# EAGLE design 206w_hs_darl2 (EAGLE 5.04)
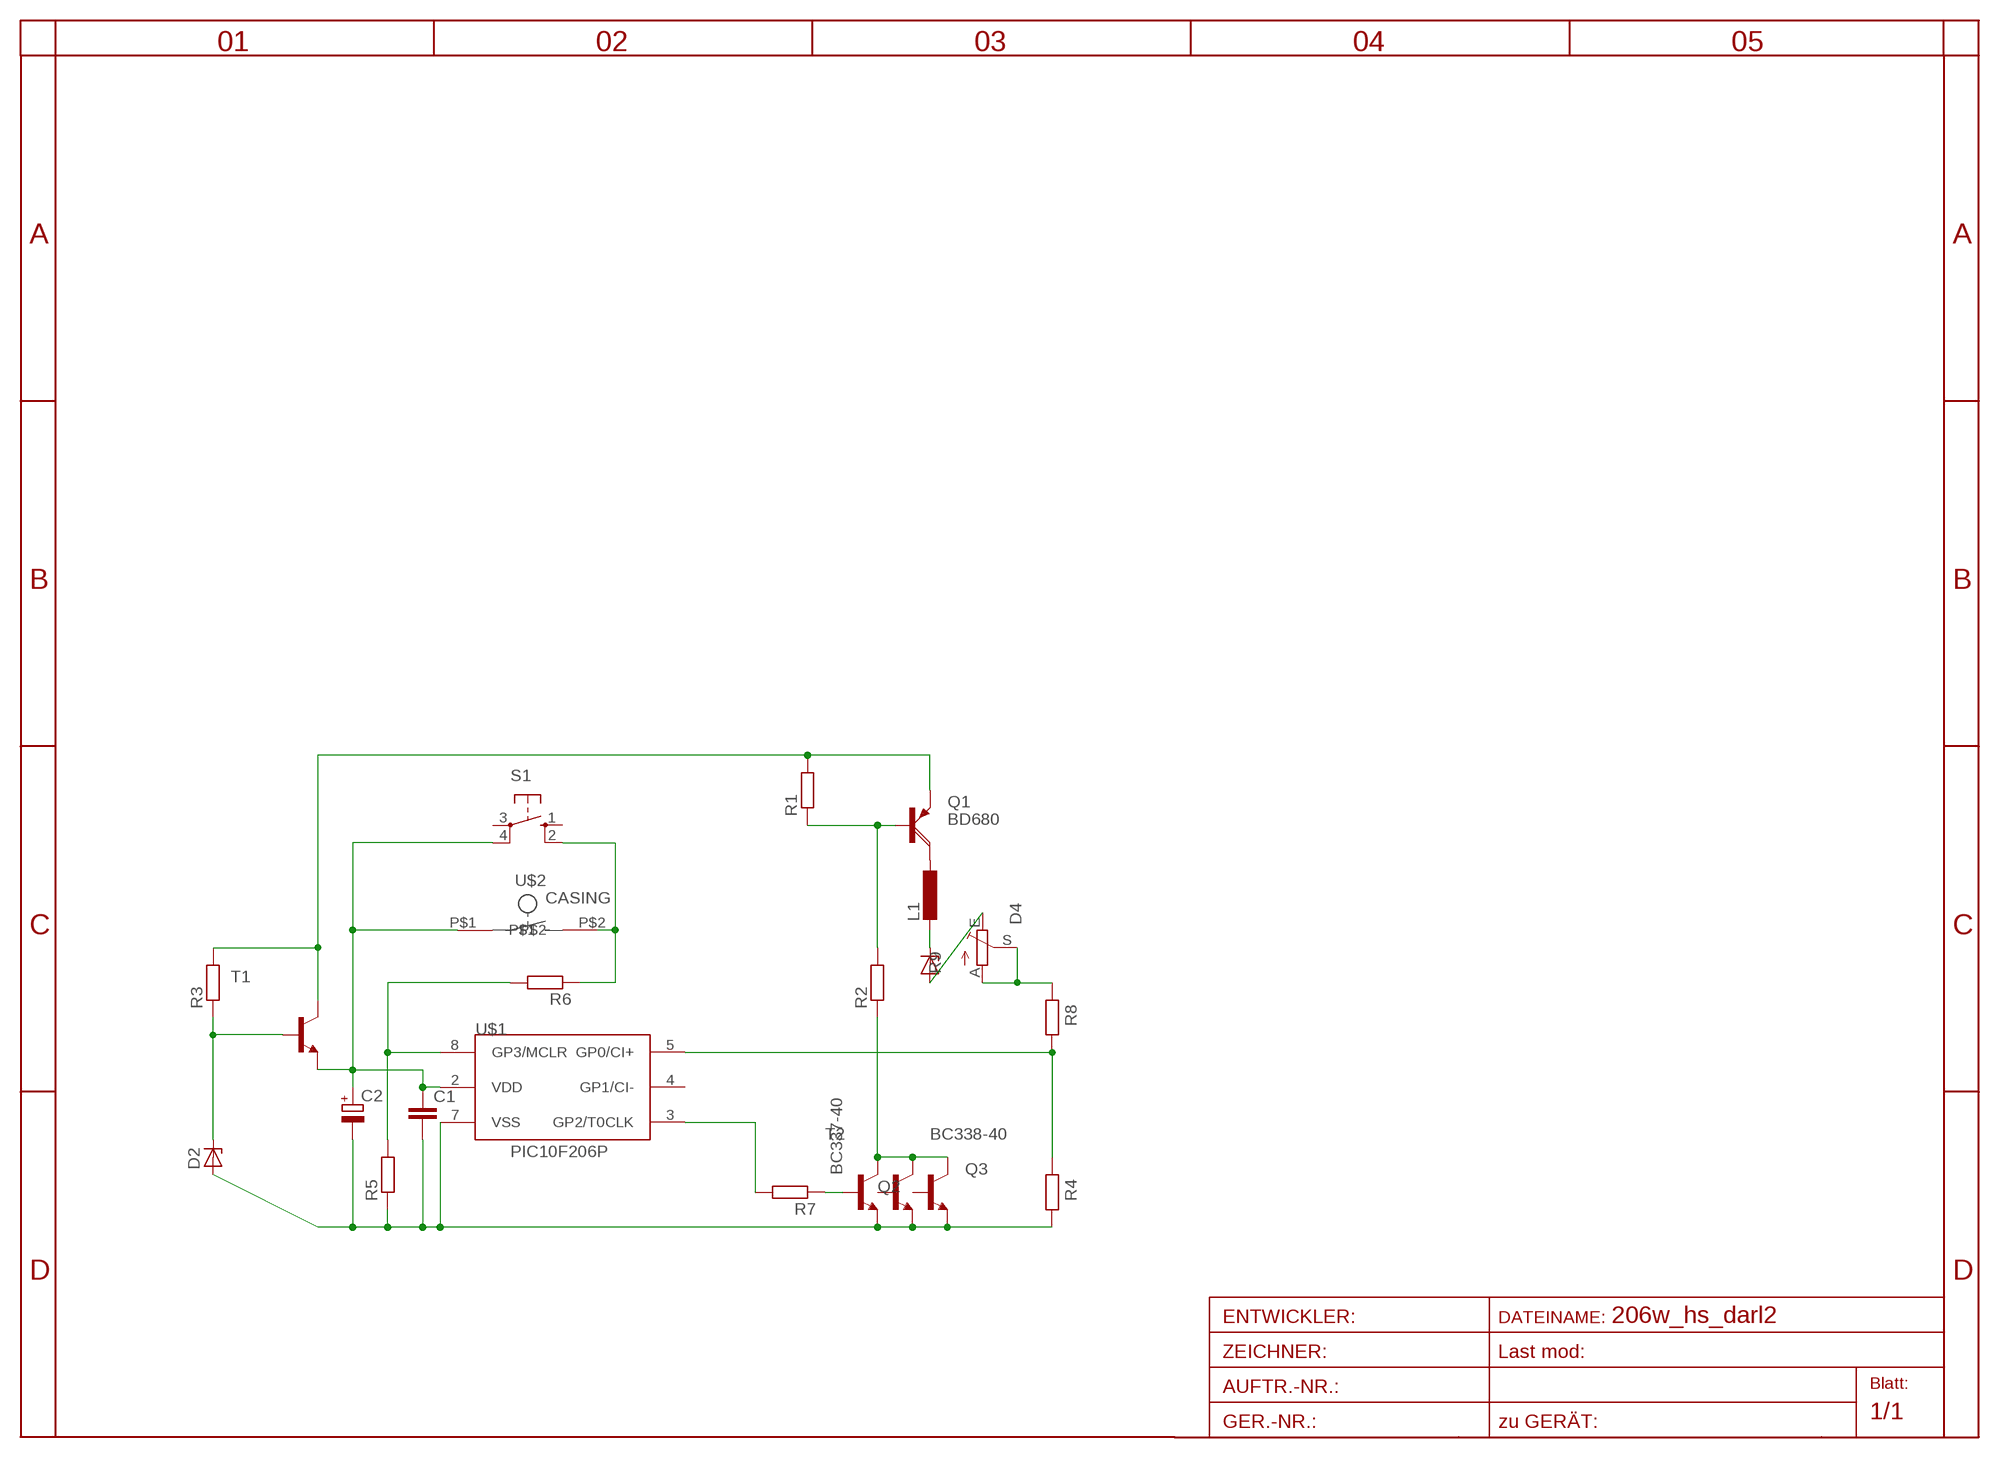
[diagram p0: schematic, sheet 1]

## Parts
C1  C-EU025-025X050  [C025-025X050]
C2  CPOL-EUE2.5-5  [E2,5-5]
D2  ZENER-DIODEZD-7.5  [ZDIO-7.5]
D4  ZENER-DIODEZD-12.5  [ZDIO12.5]
L1  L-EU2200-12.7  [2200-12.7]
Q1  BD680  [TO126AV]
Q2  BC337-40  [TO92]
Q3  BC338-40  [TO92-EBC]
R1  R-EU_0204/7  [0204/7]
R2  R-EU_0204/7  [0204/7]
R3  R-EU_0204/7  [0204/7]
R4  R-EU_0204/7  [0204/7]
R5  R-EU_0204/7  [0204/7]
R6  R-EU_0204/7  [0204/7]
R7  R-EU_0204/7  [0204/7]
R8  R-EU_0204/7  [0204/7]
R9  TRIM_EU-CA6V  [CA6V]
S1  10-XX  [B3F-10XX]
T1  -NPN-TO92-BCE  [TO92-BCE]
T2  -NPN-TO92-BCE  [TO92-BCE]
U$1  PIC10F206P  [DIL8]
U$2  CASING  [CASING]

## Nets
GND: C1.2 C2.- D2.A Q2.1(E) Q3.E R4.1 R5.1 T2.E U$1.7(VSS)
N$1: R8.2 R9.A R9.S
N$2: C1.1 C2.+ S1.4(P1) T1.E U$1.2(VDD) U$2.P$1
N$3: L1.1 Q1.C
N$5: R5.2 R6.2 U$1.8(GP3/MCLR)
N$7: R6.1 S1.2(S1) U$2.P$2
N$8: D2.C R3.1 T1.B
N$9: R7.2 U$1.3(GP2/T0CLK)
N$10: Q2.2(B) R7.1
N$11: Q2.3(C) Q3.C R2.1 T2.C
N$12: D4.A R9.E
N$13: Q1.B R1.1 R2.2
N$14: R4.2 R8.1 U$1.5(GP0/CI+)
N$15: D4.C L1.2
V60: Q1.E R1.2 R3.2 T1.C
Unconnected: Q3.B S1.1(S) S1.3(P) T2.B U$1.4(GP1/CI-)

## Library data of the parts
C1 = rcl:C-EU: CAPACITOR, European symbol
C2 = rcl:CPOL-EU: POLARIZED CAPACITOR, European symbol
D2 D4 = diode-1:ZENER-DIODE: Z-Diode
L1 = rcl-2:L-EU: INDUCTOR, European symbol
Q1 = transistor-power:BD680: PNP DARLINGTON TRANSISTOR
Q2 = transistor-npn:BC337*: NPN Transistor
Q3 = transistor-npn:BC338*: NPN Transistor
R1-R8 = rcl:R-EU_: RESISTOR, European symbol
R9 = pot:TRIM_EU-: POTENTIOMETER
S1 = switch-omron:10-XX: OMRON SWITCH
T1 T2 = transistor-neu-to92:*-NPN-: NPN Transistror
U$1 = microchip-5:PIC10F2*: uPC nW 0,25/0,5k Program Flash memory Comparator
U$2 = button:CASING

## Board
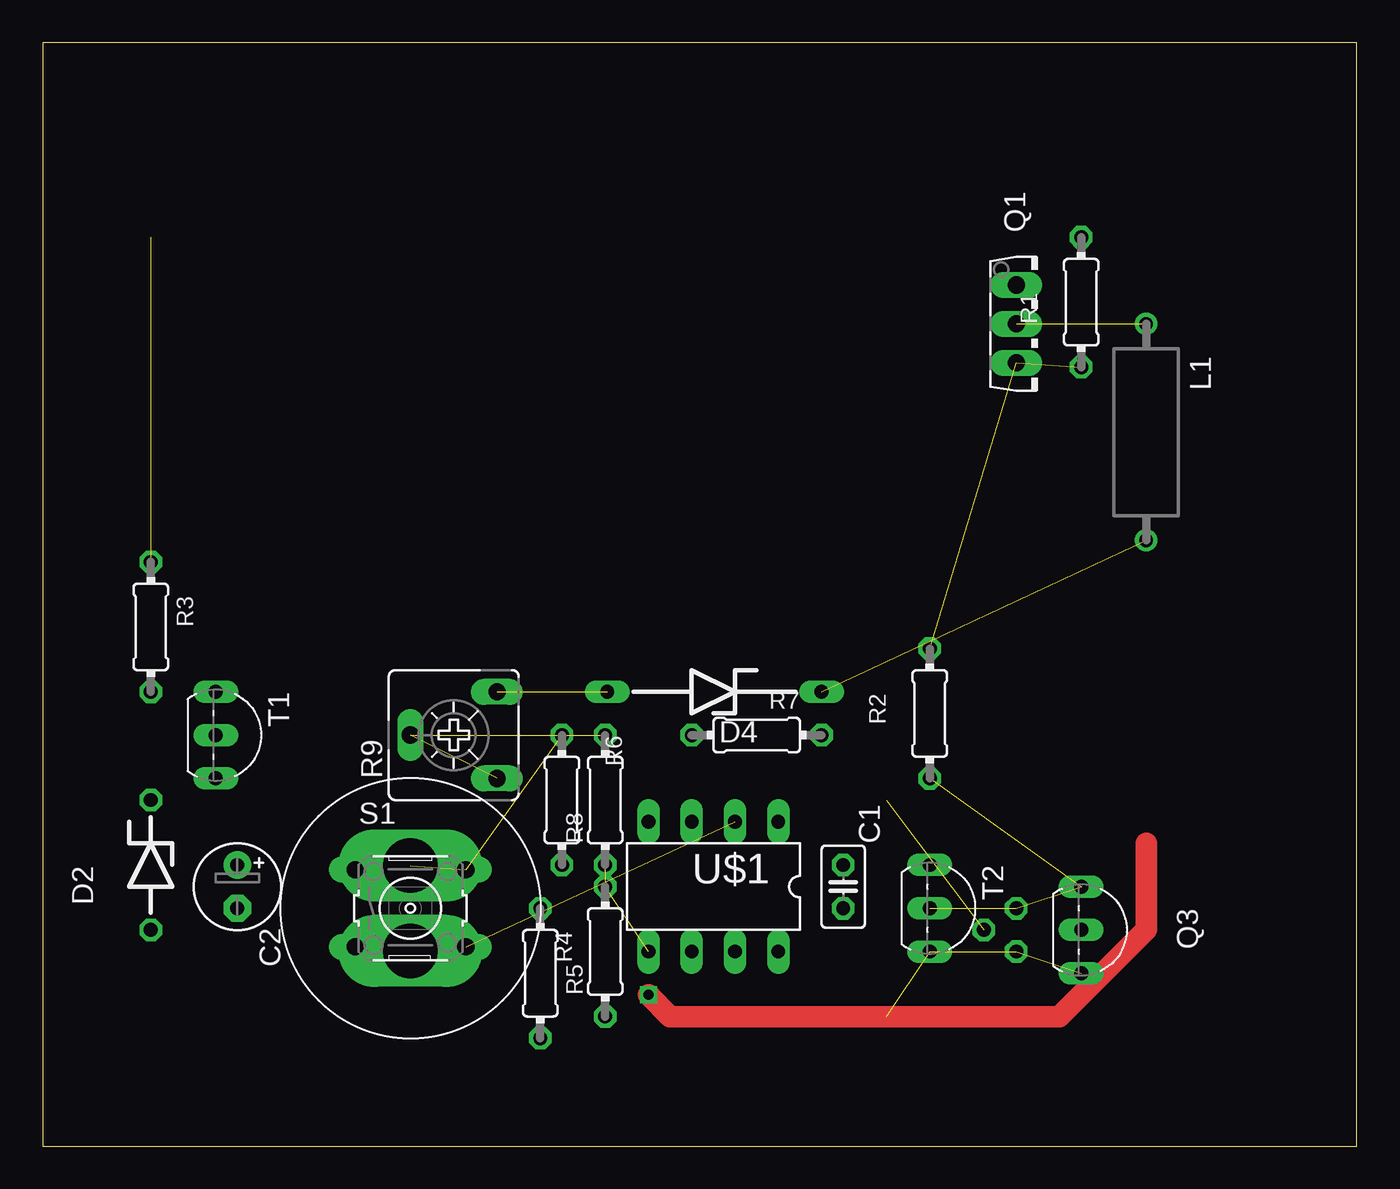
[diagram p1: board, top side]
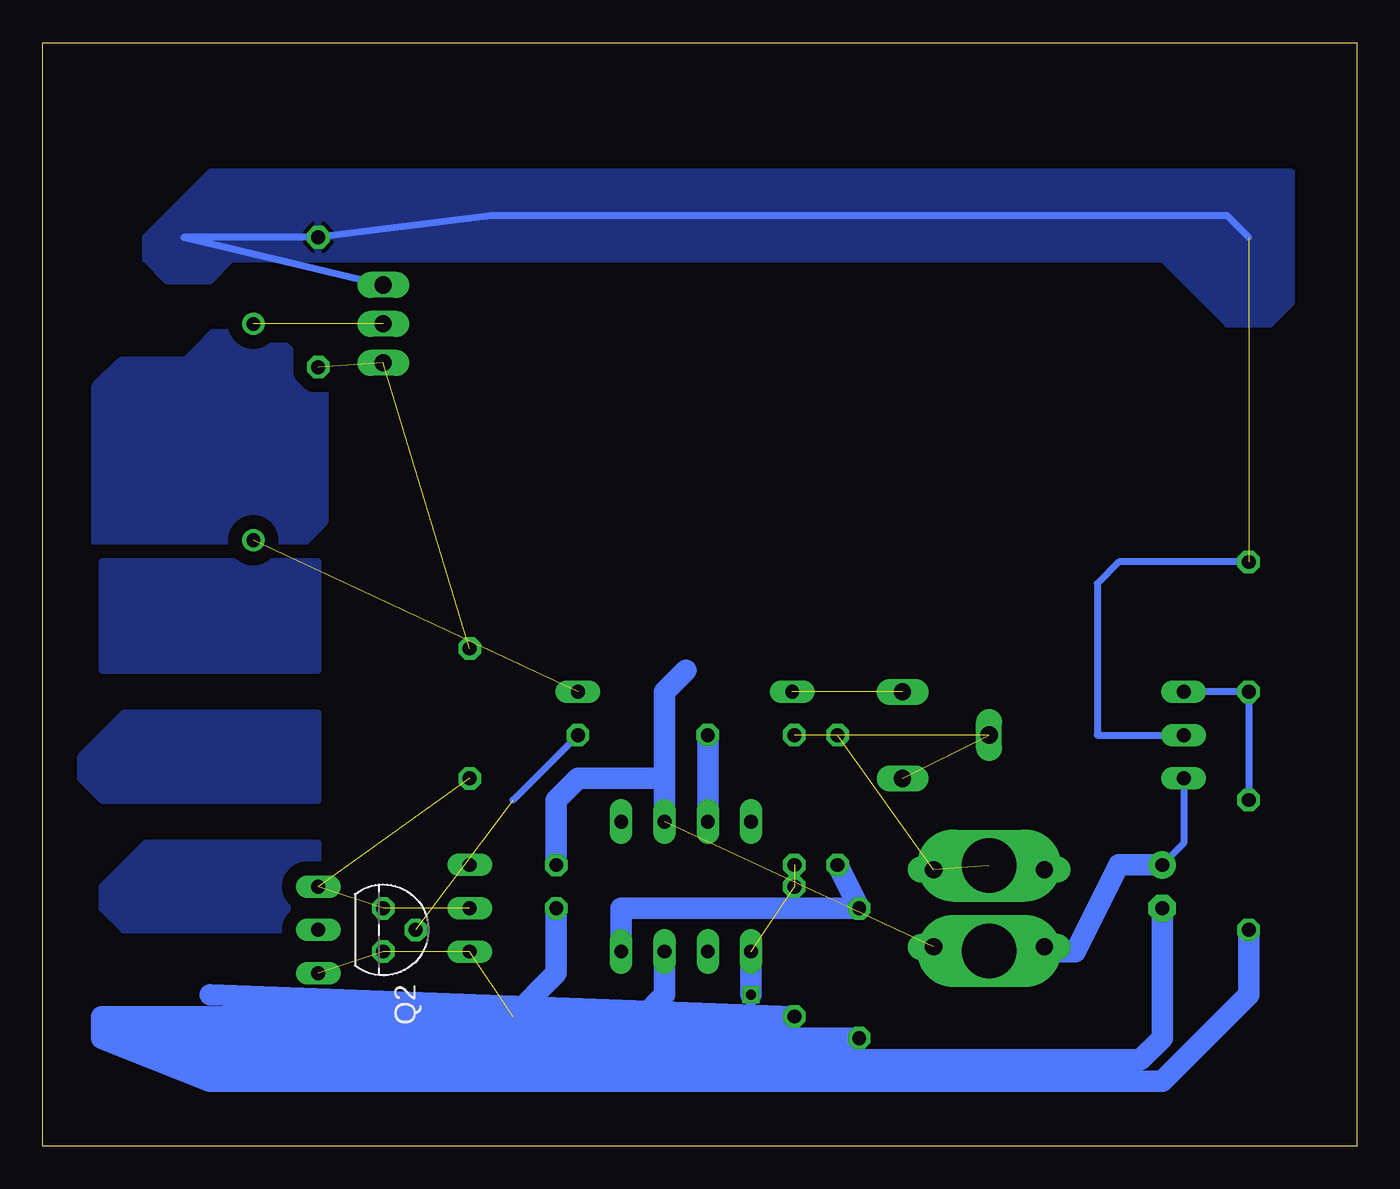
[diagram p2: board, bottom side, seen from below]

Size 77.14 x 64.76 mm. Coordinates in mm from the lower left corner, seen from the top.
Outline: 0,0 77.14,0 77.14,64.76 0,64.76 0,0
Copper layers (1*16): Top 0.035mm / dielectric 1.5mm / Bottom 0.035mm
Design rules "default": minimum track width 10mil, minimum drill 24mil, track to track 8mil, track to pad 8mil, pad to pad 8mil, via to via 8mil, smd to smd 8mil, copper to edge 40mil, drill to drill 8mil, minimum pad ring 10mil, minimum via ring 8mil, stop-mask expansion 4mil, vias tented up to drill 0mil, thermal gap 10mil

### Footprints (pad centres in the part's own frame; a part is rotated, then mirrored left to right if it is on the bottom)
C025-025X050 = drill 0.813 octagon: 1 -1.27,0; 2 1.27,0
E2,5-5 = drill 0.813 pad 1.6 round: + -1.27,0 | drill 0.813 pad 1.6 octagon: - 1.27,0
ZDIO-7.5 = drill 0.813 octagon: A 3.81,0; C -3.81,0
ZDIO12.5 = drill 0.813 long: A 6.223,0; C -6.35,0
2200-12.7 = drill 0.8 pad 1.27 round: 1 -6.35,0; 2 6.35,0
TO126AV = drill 1.016 long: B 2.286,-1.27; C 0,-1.27; E -2.286,-1.27
TO92 = drill 0.813 octagon: 1 1.27,0; 2 0,1.905; 3 -1.27,0
TO92-EBC = drill 0.813 long: B 0,-1.27; C -2.54,-1.27; E 2.54,-1.27
0204/7 = drill 0.813 octagon: 1 -3.81,0; 2 3.81,0
CA6V = drill 1.016 long: A -2.54,-2.54; E 2.54,-2.54; S 0,2.54
B3F-10XX = drill 1.016 long: 1 -3.251,2.261; 2 3.251,2.261; 3 -3.251,-2.261; 4 3.251,-2.261
TO92-BCE = drill 0.813 long: B -2.54,0; C 0,0; E 2.54,0
DIL8 = drill 0.813 long: 1 -3.81,-3.81; 2 -1.27,-3.81; 3 1.27,-3.81; 4 3.81,-3.81; 5 3.81,3.81; 6 1.27,3.81; 7 -1.27,3.81; 8 -3.81,3.81
CASING = drill 3.2 pad 3.81 long: P$1 -2.5,0; P$2 2.5,0

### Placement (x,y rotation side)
C1  46.99,15.24 270 top
C2  11.43,15.24 270 top
D2  6.35,16.51 270 top
D4  39.37,26.67 180 top
L1  64.77,41.91 270 top
Q1  58.42,48.26 270 top
Q2  57.15,12.7 270 bottom
Q3  62.23,12.7 270 top
R1  60.96,49.53 90 top
R2  52.07,25.4 90 top
R3  6.35,30.48 90 top
R4  33.02,11.43 90 top
R5  29.21,10.16 90 top
R6  30.48,20.32 270 top
R7  41.91,24.13 180 top
R8  33.02,20.32 90 top
R9  24.13,24.13 90 top
S1  21.59,13.97 0 top
T1  10.16,24.13 270 top
T2  52.07,13.97 270 top
U$1  39.37,15.24 180 top
U$2  21.59,13.97 90 top

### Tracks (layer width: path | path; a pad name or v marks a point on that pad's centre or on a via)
GND  (3 unrouted)
  Bottom 1.27: D2.A 6.35,8.89 11.43,3.81 67.31,3.81 73.66,6.35 73.66,7.62 | 73.66,7.62 R4.1 67.31,8.89 | C2.- 11.43,6.35 12.7,5.08 67.31,5.08 73.66,7.62 | 73.66,7.62 68.58,6.35 R5.1 | U$1.7 40.64,8.89 41.91,7.62 49.53,7.62 | 73.66,7.62 49.53,7.62 | C1.2 46.99,10.16 49.53,7.62
N$1  (2 unrouted)
  pour Bottom (isolate 0.813, rank 3): 60.96,25.4 72.39,25.4 74.93,22.86 74.93,21.59 73.66,20.32 60.96,20.32
N$2  (1 unrouted)
  Bottom 0.406: T1.E 10.16,17.78 C2.+
  Bottom 1.27: C2.+ 13.97,16.51 16.51,11.43 24.56,11.43 | 24.56,11.43 S1.4 | 24.56,11.43 21.63,11.43 U$2.P$1 | 40.64,21.59 40.64,26.67 39.37,27.94 | U$1.2 40.64,21.59 | C1.1 46.99,20.32 45.72,21.59 40.64,21.59
N$3  (1 unrouted)
N$4
  pour Bottom (isolate 0.813, rank 5): 66.04,48.26 64.77,46.99 63.5,46.99 60.96,44.45 60.96,36.83 62.23,35.56 73.66,35.56 73.66,44.45 72.39,45.72 68.58,45.72
N$5
  Bottom 1.27: U$1.8 43.18,13.97 R5.2 R6.2
N$6
  pour Bottom (isolate 0.813, rank 4): 60.96,34.29 73.66,34.29 73.66,27.94 60.96,27.94
N$7  (2 unrouted)
N$8
  Bottom 0.406: T1.B R3.1 D2.C
N$9
  Bottom 1.27: U$1.3 R7.2
N$10  (1 unrouted)
  Bottom 0.406: R7.1 49.53,20.32
N$11  (3 unrouted)
N$12  (1 unrouted)
N$13  (2 unrouted)
N$14  (via drill 0.6)  (2 unrouted)
  Top 1.27: v35.56,8.89 36.83,7.62 59.69,7.62 64.77,12.7 64.77,17.78
  Bottom 1.27: v35.56,8.89 U$1.5
  pour Bottom (isolate 0.813, rank 3): 60.96,17.78 71.12,17.78 73.66,15.24 73.66,13.97 72.39,12.7 62.23,12.7 60.96,13.97
N$15  (1 unrouted)
V60  (1 unrouted)
  Bottom 0.406: 6.35,53.34 7.62,54.61 50.8,54.61 R1.2 68.83,53.34 Q1.E | R3.2 13.97,34.29 15.24,33.02 15.24,24.13 T1.C
  pour Bottom (isolate 0.813, rank 5): 3.81,57.15 67.31,57.15 71.12,53.34 71.12,52.07 69.85,50.8 67.31,50.8 66.04,52.07 11.43,52.07 7.62,48.26 5.08,48.26 3.81,49.53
